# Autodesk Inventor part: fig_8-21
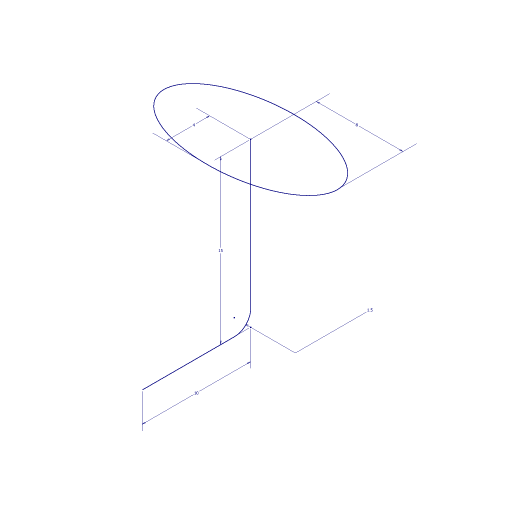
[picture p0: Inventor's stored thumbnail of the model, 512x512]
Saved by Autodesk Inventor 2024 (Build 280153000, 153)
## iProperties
Created: 2013-07
Part Number: fig_8-21
Material: Generic
Document SubType Name: Modeling
Designer: CADCIM
Density: 1 g/cm^3
Appearance: Default
Author: CADCIM
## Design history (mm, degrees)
sketch "Sketch1" dims "d0" = 8, "d1" = 4
  geometry: 2 further points; 1 other entity
  constraints: 1 coincident, 2 other
sketch "Sketch2"
  geometry: L1 (0, 0)-(0, -13.5); L2 (-1.5, -15)-(-10, -15); A1 r 1.5 centre (-1.5, -13.5) between (-1.5, -15) and (0, -13.5); 1 further point
  constraints: 4 end point, 2 point on circle, 2 point on line, 2 tangent, 1 centre point, 1 perpendicular, 1 vertical
  dimensions: "d2" = 15 distance of L1.start point (0, -15); "d3" = 10 distance of point (0, -15) L2.end; "d4" = 1.5 radius of A1
